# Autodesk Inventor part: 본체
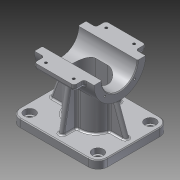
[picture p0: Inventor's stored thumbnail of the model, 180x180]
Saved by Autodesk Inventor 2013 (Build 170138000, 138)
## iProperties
Company: 한국ATC센터
Created: 2014-02
Part Number: 본체
Document SubType Name: Modeling
Designer: KYOUNG IL JANG
Density: 2.71 g/cm^3
Material: 알루미늄-6061
Vendor: CBT Solutions
Mass: 556.916 g
Surface Area: 547.387 cm^2
Volume: 205.504 cm^3
Author: KYOUNG IL JANG
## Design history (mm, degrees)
sketch "스케치1"
  geometry: L1 (-55, 45)-(55, 45); L2 (55, 45)-(55, -45); L3 (55, -45)-(-55, -45); L4 (-55, -45)-(-55, 45); 3 further points
  constraints: 8 end point, 2 midpoint, 2 parallel, 1 horizontal, 1 horizontal alignment, 1 perpendicular, 1 vertical alignment
  dimensions: "d0" = 110 distance of L2.end L3.end; "d1" = 90 distance of L1.end L2.end
extrude "돌출1" new body sketch "스케치1" distance "d2" = 10; taper "d3" = 0 deg
sketch "스케치2"
  geometry: L1 (45, 0)-(-45, 0) reference; C1 r 32.5 at (0, 80); 2 further points
  constraints: 1 centre point, 1 midpoint, 1 vertical alignment
  dimensions: "d4" = 65 diameter of C1; "d5" = 80 distance from line of C1.centre L1
extrude "돌출2" join sketch "스케치2" stored distance "d6" = 75; taper "d7" = 0 deg
sketch "스케치3"
  geometry: L1 (-7.5, -20)-(7.5, -20); L2 (7.5, 20)-(-7.5, 20); A1 r 20 centre (7.5, 0) between (7.5, -20) and (7.5, 20); A2 r 20 centre (-7.5, 0) between (-7.5, 20) and (-7.5, -20); 2 further points
  constraints: 4 end point, 4 point on circle, 4 tangent, 2 centre point, 1 horizontal, 1 horizontal alignment, 1 midpoint, 1 parallel, 1 vertical alignment
  dimensions: "d8" = 20 radius of A2; "d9" = 55 dimension on A1 A2
extrude "돌출3" join sketch "스케치3" stored distance "d10" = 75; taper "d11" = 0 deg
fillet "모깎기1" dims "d12" = 12
sketch "스케치4"
  geometry: L1 (-55, 0)-(-55, 10) reference; L2 (37.5, 47.5)-(-37.5, 47.5) reference; L3 (-48, 10)-(-34.351, 47.5); 1 further point
  constraints: 2 end point, 1 horizontal alignment, 1 point on line
  dimensions: "d105" = 7 distance from line of L3.start L1; "d106" = 110 deg dimension on L3.start L3.end L1.end
sketch "스케치5"
  geometry: L1 (-45, 0)-(-45, 10) reference; L2 (-38, 10)-(-28.433, 64.258); 2 further points
  constraints: 2 end point, 1 horizontal alignment, 2 other
  dimensions: "d107" = 7 distance from line of L2.start L1; "d108" = 100 deg dimension on L2.start L2.end L1.end
feature "리브1" dims "d15" = 1, "d16" = 6, "d17" = 0
feature "리브2" dims "d18" = 1, "d19" = 6, "d20" = 0
fillet "모깎기3" dims "d22" = 3
fillet "모깎기4" dims "d23" = 3
fillet "모깎기5" dims "d24" = 3
fillet "모깎기6" dims "d25" = 3
fillet "모깎기7" dims "d26" = 3
fillet "모깎기12" dims "d109" = 2
sketch "스케치6"
  geometry: A1 r 12 centre (43, -33) between (43, -45) and (55, -33) reference; A2 r 12 centre (-43, -33) between (-55, -33) and (-43, -45) reference; A3 r 12 centre (-43, 33) between (-43, 45) and (-55, 33) reference; A4 r 12 centre (43, 33) between (55, 33) and (43, 45) reference; 1 further point
hole "구멍7" sketch "스케치6" at (43, -33), (-43, -33), (-43, 33), (43, 33) diameter "d110" = 9; stored, may be unused: countersink angle "d114" = 90 deg, drill point angle "d116" = 118 deg; dims "d111" = 6, "d112" = 14, "d113" = 6.6, "d115" = 8
hole "구멍2" diameter "d37" = 45; stored, may be unused: countersink angle "d41" = 90 deg, drill point angle "d43" = 118 deg; dims "d35" = 10, "d36" = 10, "d38" = 6, "d39" = 4, "d40" = 2, "d42" = 8
sketch "스케치7"
  geometry: C1 r 22.5 at (0, 0) reference; 2 further points
  dimensions: "d44" = 135 deg dimension on C1.centre point (-18.738, 18.738) point (80, 0); "d45" = 26.5 distance of point (-18.738, 18.738) C1.centre
hole "구멍3" sketch "스케치7" at (-18.738, 18.738) diameter "d46" = 2.459; stored, may be unused: countersink angle "d50" = 90 deg, drill point angle "d52" = 118 deg; dims "d47" = 8, "d48" = 4, "d49" = 2, "d51" = 10
node "작업 평면1"
sketch "스케치8"
  geometry: C1 r 10 at (0, 0); 1 further point
  constraints: 1 centre point, 1 coincident
  dimensions: "d57" = 20 diameter of C1
extrude "돌출4" join sketch "스케치8" stored distance "d58" = 75; taper "d59" = 0 deg
hole "구멍4" diameter "d62" = 8.376; stored, may be unused: countersink angle "d66" = 90 deg, drill point angle "d68" = 118 deg; dims "d60" = 10, "d61" = 10, "d63" = 7, "d64" = 4, "d65" = 2, "d67" = 10
chamfer "모따기1" distance "d69" = 1; stored, may be unused: second distance "d70" = 2, angle "d71" = 45 deg
fillet "모깎기9" dims "d72" = 3
sketch "스케치9"
  geometry: L1 (-31.623, 87.5)-(-45, 87.5); L2 (-45, 87.5)-(-45, 72.5); L3 (-45, 72.5)-(-31.623, 72.5); A1 r 32.5 centre (0, 80) between (-31.623, 87.5) and (-31.623, 72.5) reference; 1 further point
  constraints: 6 end point, 2 parallel, 2 point on circle, 1 horizontal, 1 perpendicular
  dimensions: "d73" = 15 distance of L1.end L2.end; "d74" = 45 distance from line of A1.centre L2
extrude "돌출5" join sketch "스케치9" stored distance "d75" = 50; taper "d76" = 0 deg
fillet "모깎기10" dims "d77" = 3
fillet "모깎기11" dims "d78" = 3
sketch "스케치10"
  geometry: L1 (-61.625, 62.366)-(0, 62.366); L2 (0, 62.366)-(0, -62.366); L3 (0, -62.366)-(-61.625, -62.366); L4 (-61.625, -62.366)-(-61.625, 62.366); C1 r 32.5 at (0, 0) reference; 2 further points
  constraints: 8 end point, 2 parallel, 1 coincident, 1 horizontal, 1 midpoint, 1 perpendicular
extrude "돌출6" cut sketch "스케치10" stored distance "d79" = 10; taper "d80" = 0 deg
node "작업 평면2"
sketch "스케치11"
  geometry: L1 (-7.5, -15)-(7.5, -15); L2 (7.5, 15)-(-7.5, 15); A1 r 15 centre (7.5, 0) between (7.5, -15) and (7.5, 15); A2 r 15 centre (-7.5, 0) between (-7.5, 15) and (-7.5, -15); 2 further points
  constraints: 4 end point, 4 point on circle, 4 tangent, 2 centre point, 1 horizontal, 1 horizontal alignment, 1 midpoint, 1 parallel, 1 vertical alignment
  dimensions: "d82" = 15 radius of A2; "d117" = 45 dimension on A2 A1
extrude "돌출7" cut sketch "스케치11" stored distance "d83" = 10; taper "d84" = 0 deg
sketch "스케치12"
  geometry: 1 further point
hole "구멍5" sketch "스케치12" at (0, 0) diameter "d85" = 12; stored, may be unused: countersink angle "d89" = 90 deg, drill point angle "d91" = 118 deg; dims "d86" = 6, "d87" = 38, "d88" = 10, "d90" = 8
sketch "스케치13"
  geometry: L1 (-15.5, -12.5)-(-59.5, -12.5) reference; 3 further points
  constraints: 1 horizontal alignment
  dimensions: "d92" = 35 distance of point (-20, -5.5) point (-55, -5.5); "d93" = 17.5 horizontal distance of point (-37.5, 32.5) point (-55, -5.5) (= 0.5 x d92); "d94" = 7 distance from line of L1 point (-55, -5.5)
hole "구멍6" sketch "스케치13" at (-55, -5.5), (-20, -5.5) diameter "d95" = 3.242; stored, may be unused: countersink angle "d99" = 90 deg, drill point angle "d101" = 118 deg; dims "d96" = 6, "d97" = 38, "d98" = 10, "d100" = 8
sketch "스케치14"
  geometry: C1 r 10 at (0, 0); 1 further point
  constraints: 1 centre point, 1 coincident
  dimensions: "d102" = 20 diameter of C1
extrude "돌출8" cut sketch "스케치14" distance "d103" = 5; taper "d104" = 0 deg
chamfer "모따기2" distance "d118" = 1; stored, may be unused: second distance "d119" = 2, angle "d120" = 45 deg
node "솔리드1"
mirror "대칭1"
mirror "대칭2"
pattern_circular "원형 패턴1" dims angle "d54" = 360 deg
mirror "대칭5"
mirror "대칭6"
mirror "대칭7"
other parameters: "d56" = -117
